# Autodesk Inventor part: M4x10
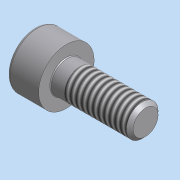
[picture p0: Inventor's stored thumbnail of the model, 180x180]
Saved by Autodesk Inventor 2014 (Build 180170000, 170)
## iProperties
Company: 한국ATC센터
Created: 2015-05
Part Number: M4x10
Document SubType Name: 모델링
Designer: KYOUNG IL JANG
Vendor: CBT Solutions
Material: 일반
Appearance: 기본값
Author: KYOUNG IL JANG
Comments: 파생
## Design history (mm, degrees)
node "KS B 1003 - 미터 M 4 x 10" dims "d0" = 10
node "솔리드1"
node "솔리드 본체"
node "곡면 본체"
feature "Solid1::KS B 1003 - 미터 M 4 x 10" dims "d0" = 10
tag "피쳐 태그1"
